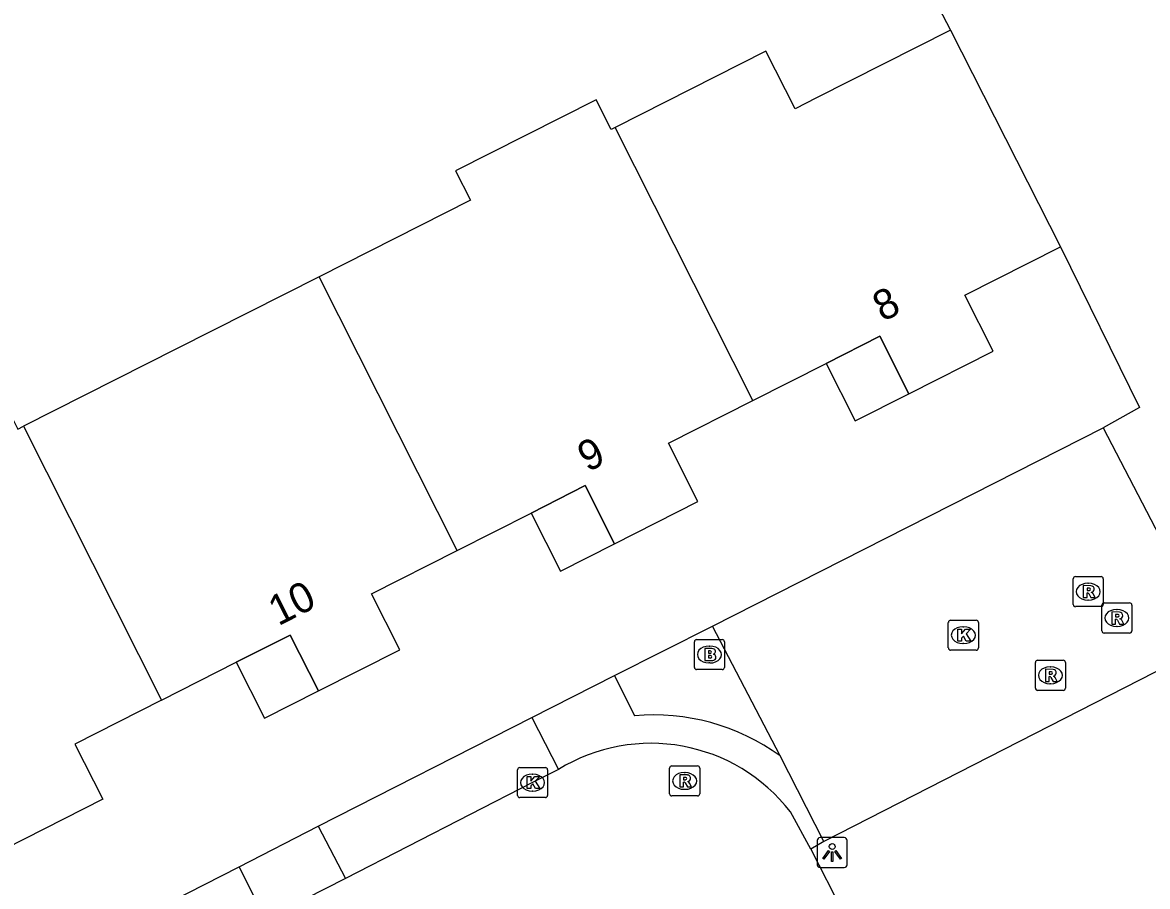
# Model space of a CAD drawing. Extents: x 162722 to 165099, y 384721 to 386283.
# Drawn here: x 163760.63 to 163798.08, y 385010.64 to 385039.4 of the extents above; entities that cross this region are included whole.
import ezdxf

# ---------------------------------------------------------------- set-up
doc = ezdxf.new("R2010")
doc.units = 0
for name, color, linetype in [('IMGEO_Brandkraan', 7, 'Continuous'), ('IMGEO_Groenvoorziening', 7, 'Continuous'), ('IMGEO_Kolk', 7, 'Continuous'), ('IMGEO_Lichtpunt', 7, 'Continuous'), ('IMGEO_Pand', 7, 'Continuous'), ('IMGEO_Pand_nummerreeks', 7, 'Continuous'), ('IMGEO_Pand_overbouw', 7, 'Continuous'), ('IMGEO_Rijbaan_lokaal_open', 7, 'Continuous'), ('IMGEO_Rioolput', 7, 'Continuous'), ('IMGEO_Voetpad_open', 7, 'Continuous')]:
    doc.layers.add(name, color=color, linetype=linetype)

msp = doc.modelspace()

# ---------------------------------------------------------------- linework, layer by layer
at = {"layer": 'IMGEO_Brandkraan'}
for p, q in [((163783.072, 385018.863), (163783.924, 385018.863)), ((163782.997, 385017.937), (163782.997, 385018.789)), ((163783.485, 385018.643), (163783.51, 385018.643)), ((163783.998, 385018.789), (163783.998, 385017.937)), ((163783.924, 385017.863), (163783.072, 385017.863)), ((163783.508, 385018.083), (163783.483, 385018.083))]:
    msp.add_line(p, q, dxfattribs=at)
for points in [[(163783.072, 385018.863), (163783.924, 385018.863)], [(163782.997, 385017.937), (163782.997, 385018.789)], [(163783.345, 385018.563), (163783.345, 385018.163), (163783.558, 385018.163)], [(163783.576, 385018.563), (163783.345, 385018.563)], [(163783.524, 385018.482), (163783.47, 385018.482), (163783.47, 385018.406)], [(163783.998, 385018.789), (163783.998, 385017.937)], [(163783.47, 385018.406), (163783.523, 385018.406)], [(163783.532, 385018.33), (163783.47, 385018.33), (163783.47, 385018.249)], [(163783.47, 385018.249), (163783.532, 385018.249)], [(163783.924, 385017.863), (163783.072, 385017.863)]]:
    msp.add_lwpolyline(points, dxfattribs=at)
for centre, radius, start, end in [((163783.074, 385018.787), 0.0765, 91.552, 178.448), ((163783.074, 385018.787), 0.0765, 91.552, 178.448), ((163783.922, 385018.787), 0.0765, 1.552, 88.448), ((163783.922, 385018.787), 0.0765, 1.552, 88.448), ((163783.525, 385018.444), 0.0379, 267.8285, 90.9355), ((163783.58, 385018.418), 0.145, 59.4692, 91.5367), ((163783.605, 385018.465), 0.0922, 285.5137, 58.1501), ((163783.533, 385018.289), 0.0404, 269.8759, 90.5077), ((163783.564, 385018.414), 0.251, 268.6676, 293.5347), ((163783.61, 385018.273), 0.105, 301.3115, 78.989), ((163783.074, 385017.939), 0.0765, 181.552, 268.448), ((163783.074, 385017.939), 0.0765, 181.552, 268.448), ((163783.922, 385017.939), 0.0765, 271.552, 358.448), ((163783.922, 385017.939), 0.0765, 271.552, 358.448)]:
    msp.add_arc(centre, radius, start, end, dxfattribs=at)
for centre, major_axis, ratio, start_param, end_param in [((163783.484, 385018.363), (-0.387, 0.002), 0.722429, 4.712389, 7.853982), ((163783.509, 385018.363), (-0.39, 0.002), 0.717154, 1.570796, 4.712389)]:
    msp.add_ellipse(centre, major_axis=major_axis, ratio=ratio, start_param=start_param, end_param=end_param, dxfattribs=at)
at = {"layer": 'IMGEO_Groenvoorziening'}
for points in [[(163783.871, 385053.812), (163791.526, 385039.145)], [(163795.181, 385031.929), (163797.817, 385026.586), (163796.607, 385025.906)]]:
    msp.add_lwpolyline(points, dxfattribs=at)
at = {"layer": 'IMGEO_Kolk'}
for p, q in [((163791.449, 385018.582), (163791.449, 385019.434)), ((163791.524, 385019.508), (163792.376, 385019.508)), ((163791.937, 385019.288), (163791.962, 385019.288)), ((163792.45, 385019.434), (163792.45, 385018.582)), ((163792.376, 385018.508), (163791.524, 385018.508)), ((163791.96, 385018.728), (163791.935, 385018.728)), ((163777.11, 385013.676), (163777.11, 385014.528)), ((163777.185, 385014.602), (163778.037, 385014.602)), ((163777.598, 385014.382), (163777.623, 385014.382)), ((163778.111, 385014.528), (163778.111, 385013.676)), ((163778.037, 385013.602), (163777.185, 385013.602)), ((163777.621, 385013.822), (163777.596, 385013.822))]:
    msp.add_line(p, q, dxfattribs=at)
for points in [[(163791.449, 385018.582), (163791.449, 385019.434)], [(163791.524, 385019.508), (163792.376, 385019.508)], [(163792.45, 385019.434), (163792.45, 385018.582)], [(163791.77, 385019.208), (163791.893, 385019.208), (163791.893, 385019.057), (163792.023, 385019.208), (163792.187, 385019.208), (163792.041, 385019.057), (163792.194, 385018.808), (163792.042, 385018.808), (163791.957, 385018.972), (163791.893, 385018.905), (163791.893, 385018.808), (163791.77, 385018.808), (163791.77, 385019.208)], [(163792.376, 385018.508), (163791.524, 385018.508)], [(163777.11, 385013.676), (163777.11, 385014.528)], [(163777.185, 385014.602), (163778.037, 385014.602)], [(163778.111, 385014.528), (163778.111, 385013.676)], [(163777.431, 385014.302), (163777.554, 385014.302), (163777.554, 385014.151), (163777.684, 385014.302), (163777.848, 385014.302), (163777.702, 385014.151), (163777.855, 385013.902), (163777.703, 385013.902), (163777.618, 385014.066), (163777.554, 385013.999), (163777.554, 385013.902), (163777.431, 385013.902), (163777.431, 385014.302)], [(163778.037, 385013.602), (163777.185, 385013.602)]]:
    msp.add_lwpolyline(points, dxfattribs=at)
for centre, start, end in [((163791.526, 385019.432), 91.552, 178.448), ((163791.526, 385019.432), 91.552, 178.448), ((163792.374, 385019.432), 1.552, 88.448), ((163792.374, 385019.432), 1.552, 88.448), ((163791.526, 385018.584), 181.552, 268.448), ((163791.526, 385018.584), 181.552, 268.448), ((163792.374, 385018.584), 271.552, 358.448), ((163792.374, 385018.584), 271.552, 358.448), ((163777.187, 385014.526), 91.552, 178.448), ((163777.187, 385014.526), 91.552, 178.448), ((163778.035, 385014.526), 1.552, 88.448), ((163778.035, 385014.526), 1.552, 88.448), ((163777.187, 385013.678), 181.552, 268.448), ((163777.187, 385013.678), 181.552, 268.448), ((163778.035, 385013.678), 271.552, 358.448), ((163778.035, 385013.678), 271.552, 358.448)]:
    msp.add_arc(centre, 0.0765, start, end, dxfattribs=at)
for centre, major_axis, ratio, start_param, end_param in [((163791.936, 385019.008), (-0.387, 0.002), 0.722429, 4.712389, 7.853982), ((163791.961, 385019.008), (-0.39, 0.002), 0.717154, 1.570796, 4.712389), ((163777.597, 385014.102), (-0.387, 0.002), 0.722429, 4.712389, 7.853982), ((163777.622, 385014.102), (-0.39, 0.002), 0.717154, 1.570796, 4.712389)]:
    msp.add_ellipse(centre, major_axis=major_axis, ratio=ratio, start_param=start_param, end_param=end_param, dxfattribs=at)
at = {"layer": 'IMGEO_Lichtpunt'}
for p, q in [((163787.085, 385012.177), (163787.085, 385011.37)), ((163787.085, 385012.177), (163787.085, 385011.37)), ((163787.987, 385012.272), (163787.179, 385012.272)), ((163787.987, 385012.272), (163787.179, 385012.272)), ((163788.081, 385011.37), (163788.081, 385012.177)), ((163788.081, 385011.37), (163788.081, 385012.177)), ((163787.179, 385011.276), (163787.987, 385011.276)), ((163787.179, 385011.276), (163787.987, 385011.276))]:
    msp.add_line(p, q, dxfattribs=at)
for points in [[(163787.459, 385011.841), (163787.498, 385011.813), (163787.31, 385011.551), (163787.272, 385011.578), (163787.459, 385011.841)], [(163787.561, 385011.793), (163787.608, 385011.793), (163787.608, 385011.471), (163787.561, 385011.471), (163787.561, 385011.793)], [(163787.671, 385011.813), (163787.709, 385011.84), (163787.896, 385011.578), (163787.857, 385011.55), (163787.671, 385011.813)]]:
    msp.add_lwpolyline(points, dxfattribs=at)
msp.add_circle((163787.584, 385011.975), 0.0994, dxfattribs=at)
for centre, start, end in [((163787.179, 385012.177), 90, 180), ((163787.179, 385012.177), 90, 180), ((163787.987, 385012.177), 0, 90), ((163787.987, 385012.177), 0, 90), ((163787.179, 385011.37), 180, 270), ((163787.179, 385011.37), 180, 270), ((163787.987, 385011.37), 270, 0), ((163787.987, 385011.37), 270, 360)]:
    msp.add_arc(centre, 0.0946, start, end, dxfattribs=at)
at = {"layer": 'IMGEO_Pand'}
for points in [[(163791.526, 385039.145), (163787.066, 385036.886), (163786.353, 385036.525), (163785.38, 385038.447), (163780.362, 385035.906)], [(163791.526, 385039.145), (163795.181, 385031.929)], [(163780.362, 385035.906), (163780.224, 385035.836), (163779.723, 385036.826), (163775.048, 385034.459), (163775.544, 385033.48), (163770.511, 385030.931)], [(163784.94, 385026.815), (163780.362, 385035.906)], [(163784.94, 385026.815), (163787.381, 385028.051), (163789.168, 385028.956), (163790.137, 385027.041), (163792.939, 385028.461), (163791.999, 385030.318), (163795.181, 385031.929)], [(163770.511, 385030.931), (163765.78, 385028.549), (163760.67, 385025.961)], [(163775.097, 385021.825), (163770.511, 385030.931)], [(163765.26, 385016.849), (163762.37, 385015.385), (163763.301, 385013.546), (163758.739, 385011.235), (163753.192, 385022.186), (163755.881, 385023.548), (163756.343, 385024.825), (163760.057, 385026.705), (163760.482, 385025.866), (163760.67, 385025.961)], [(163775.097, 385021.825), (163777.559, 385023.072), (163779.361, 385023.985), (163780.34, 385022.052), (163783.112, 385023.456), (163782.132, 385025.393), (163784.94, 385026.815)], [(163760.67, 385025.961), (163765.26, 385016.849)], [(163765.26, 385016.849), (163767.743, 385018.107), (163769.542, 385019.006), (163770.481, 385017.153), (163773.192, 385018.525), (163772.25, 385020.384), (163775.097, 385021.825)]]:
    msp.add_lwpolyline(points, dxfattribs=at)
at = {"layer": 'IMGEO_Pand_overbouw'}
for points in [[(163789.168, 385028.956), (163787.381, 385028.051), (163788.35, 385026.136), (163790.137, 385027.041)], [(163779.361, 385023.985), (163777.559, 385023.072), (163778.538, 385021.139), (163780.34, 385022.052)], [(163769.542, 385019.006), (163767.743, 385018.107), (163768.687, 385016.244), (163770.481, 385017.153)]]:
    msp.add_lwpolyline(points, close=True, dxfattribs=at)
at = {"layer": 'IMGEO_Rijbaan_lokaal_open'}
for points in [[(163783.595, 385019.308), (163796.607, 385025.906)], [(163796.607, 385025.906), (163799.345, 385020.634), (163799.657, 385020.033)], [(163785.848, 385014.991), (163783.595, 385019.308)], [(163800.305, 385018.786), (163787.306, 385012.139)], [(163787.306, 385012.139), (163785.848, 385014.991)], [(163778.469, 385014.536), (163777.611, 385014.102), (163771.379, 385010.915)], [(163786.877, 385011.884), (163786.194, 385013.124)], [(163786.877, 385011.884), (163792.143, 385001.568), (163792.25, 385001.396)], [(163771.379, 385010.915), (163768.724, 385009.555)]]:
    msp.add_lwpolyline(points, dxfattribs=at)
msp.add_arc((163781.548, 385009.542), 5.867, 37.6313, 121.652, dxfattribs=at)
at = {"layer": 'IMGEO_Rioolput'}
for p, q in [((163795.605, 385020.031), (163795.605, 385020.883)), ((163795.68, 385020.957), (163796.532, 385020.957)), ((163796.093, 385020.737), (163796.118, 385020.737)), ((163796.606, 385020.883), (163796.606, 385020.031)), ((163796.116, 385020.177), (163796.091, 385020.177)), ((163796.558, 385019.154), (163796.558, 385020.006)), ((163796.633, 385020.08), (163797.485, 385020.08)), ((163797.559, 385020.006), (163797.559, 385019.154)), ((163796.532, 385019.957), (163795.68, 385019.957)), ((163797.046, 385019.86), (163797.071, 385019.86)), ((163797.069, 385019.3), (163797.044, 385019.3)), ((163797.485, 385019.08), (163796.633, 385019.08)), ((163794.346, 385017.246), (163794.346, 385018.098)), ((163794.421, 385018.172), (163795.273, 385018.172)), ((163795.347, 385018.098), (163795.347, 385017.246)), ((163794.834, 385017.952), (163794.859, 385017.952)), ((163794.857, 385017.392), (163794.832, 385017.392)), ((163795.273, 385017.172), (163794.421, 385017.172)), ((163782.173, 385013.732), (163782.173, 385014.584)), ((163782.248, 385014.658), (163783.1, 385014.658)), ((163782.661, 385014.438), (163782.686, 385014.438)), ((163783.174, 385014.584), (163783.174, 385013.732)), ((163783.1, 385013.658), (163782.248, 385013.658)), ((163782.684, 385013.878), (163782.659, 385013.878))]:
    msp.add_line(p, q, dxfattribs=at)
for points in [[(163795.605, 385020.031), (163795.605, 385020.883)], [(163795.68, 385020.957), (163796.532, 385020.957)], [(163796.606, 385020.883), (163796.606, 385020.031)], [(163796.194, 385020.655), (163795.942, 385020.657), (163795.942, 385020.257)], [(163795.942, 385020.257), (163796.066, 385020.257), (163796.066, 385020.419), (163796.077, 385020.419)], [(163796.12, 385020.576), (163796.066, 385020.576), (163796.066, 385020.495)], [(163796.066, 385020.495), (163796.118, 385020.495)], [(163796.124, 385020.39), (163796.195, 385020.257), (163796.335, 385020.257), (163796.27, 385020.383)], [(163796.558, 385019.154), (163796.558, 385020.006)], [(163796.633, 385020.08), (163797.485, 385020.08)], [(163797.559, 385020.006), (163797.559, 385019.154)], [(163796.532, 385019.957), (163795.68, 385019.957)], [(163797.147, 385019.778), (163796.895, 385019.78), (163796.895, 385019.38)], [(163797.073, 385019.699), (163797.019, 385019.699), (163797.019, 385019.618)], [(163797.019, 385019.618), (163797.071, 385019.618)], [(163796.895, 385019.38), (163797.019, 385019.38), (163797.019, 385019.542), (163797.03, 385019.542)], [(163797.077, 385019.513), (163797.148, 385019.38), (163797.288, 385019.38), (163797.223, 385019.506)], [(163797.485, 385019.08), (163796.633, 385019.08)], [(163794.346, 385017.246), (163794.346, 385018.098)], [(163794.421, 385018.172), (163795.273, 385018.172)], [(163795.347, 385018.098), (163795.347, 385017.246)], [(163794.935, 385017.87), (163794.683, 385017.872), (163794.683, 385017.472)], [(163794.861, 385017.791), (163794.807, 385017.791), (163794.807, 385017.71)], [(163794.683, 385017.472), (163794.807, 385017.472), (163794.807, 385017.634), (163794.818, 385017.634)], [(163794.807, 385017.71), (163794.859, 385017.71)], [(163794.865, 385017.605), (163794.936, 385017.472), (163795.076, 385017.472), (163795.011, 385017.598)], [(163795.273, 385017.172), (163794.421, 385017.172)], [(163782.173, 385013.732), (163782.173, 385014.584)], [(163782.248, 385014.658), (163783.1, 385014.658)], [(163782.762, 385014.356), (163782.51, 385014.358), (163782.51, 385013.958)], [(163783.174, 385014.584), (163783.174, 385013.732)], [(163782.51, 385013.958), (163782.634, 385013.958), (163782.634, 385014.12), (163782.645, 385014.12)], [(163782.688, 385014.277), (163782.634, 385014.277), (163782.634, 385014.196)], [(163782.634, 385014.196), (163782.686, 385014.196)], [(163782.692, 385014.091), (163782.763, 385013.958), (163782.903, 385013.958), (163782.838, 385014.084)], [(163783.1, 385013.658), (163782.248, 385013.658)]]:
    msp.add_lwpolyline(points, dxfattribs=at)
for centre, radius, start, end in [((163795.682, 385020.881), 0.0765, 91.552, 178.448), ((163795.682, 385020.881), 0.0765, 91.552, 178.448), ((163796.53, 385020.881), 0.0765, 1.552, 88.448), ((163796.53, 385020.881), 0.0765, 1.552, 88.448), ((163796.076, 385020.366), 0.0533, 26.0293, 88.6989), ((163796.102, 385020.684), 0.19, 274.7715, 282.9687), ((163796.126, 385020.48), 0.0964, 77.0061, 93.1865), ((163796.14, 385020.537), 0.0378, 276.6634, 79.6772), ((163796.193, 385020.545), 0.109, 350.3612, 89.416), ((163796.191, 385020.545), 0.112, 277.5842, 350.9817), ((163796.175, 385020.33), 0.108, 29.5134, 73.7905), ((163795.682, 385020.033), 0.0765, 181.552, 268.448), ((163795.682, 385020.033), 0.0765, 181.552, 268.448), ((163796.53, 385020.033), 0.0765, 271.552, 358.448), ((163796.53, 385020.033), 0.0765, 271.552, 358.448), ((163796.635, 385020.004), 0.0765, 91.552, 178.448), ((163796.635, 385020.004), 0.0765, 91.552, 178.448), ((163797.483, 385020.004), 0.0765, 1.552, 88.448), ((163797.483, 385020.004), 0.0765, 1.552, 88.448), ((163797.055, 385019.807), 0.19, 274.7715, 282.9687), ((163797.079, 385019.603), 0.0964, 77.0061, 93.1865), ((163797.093, 385019.66), 0.0378, 276.6634, 79.6772), ((163797.146, 385019.668), 0.109, 350.3612, 89.416), ((163797.144, 385019.668), 0.112, 277.5842, 350.9817), ((163797.029, 385019.489), 0.0533, 26.0293, 88.6989), ((163797.128, 385019.453), 0.108, 29.5134, 73.7905), ((163796.635, 385019.156), 0.0765, 181.552, 268.448), ((163796.635, 385019.156), 0.0765, 181.552, 268.448), ((163797.483, 385019.156), 0.0765, 271.552, 358.448), ((163797.483, 385019.156), 0.0765, 271.552, 358.448), ((163794.423, 385018.096), 0.0765, 91.552, 178.448), ((163794.423, 385018.096), 0.0765, 91.552, 178.448), ((163795.271, 385018.096), 0.0765, 1.552, 88.448), ((163795.271, 385018.096), 0.0765, 1.552, 88.448), ((163794.843, 385017.899), 0.19, 274.7715, 282.9687), ((163794.867, 385017.695), 0.0964, 77.0061, 93.1865), ((163794.881, 385017.752), 0.0378, 276.6634, 79.6772), ((163794.934, 385017.76), 0.109, 350.3612, 89.416), ((163794.932, 385017.76), 0.112, 277.5842, 350.9817), ((163794.817, 385017.581), 0.0533, 26.0293, 88.6989), ((163794.916, 385017.545), 0.108, 29.5134, 73.7905), ((163794.423, 385017.248), 0.0765, 181.552, 268.448), ((163794.423, 385017.248), 0.0765, 181.552, 268.448), ((163795.271, 385017.248), 0.0765, 271.552, 358.448), ((163795.271, 385017.248), 0.0765, 271.552, 358.448), ((163782.25, 385014.582), 0.0765, 91.552, 178.448), ((163782.25, 385014.582), 0.0765, 91.552, 178.448), ((163782.761, 385014.246), 0.109, 350.3612, 89.416), ((163783.098, 385014.582), 0.0765, 1.552, 88.448), ((163783.098, 385014.582), 0.0765, 1.552, 88.448), ((163782.644, 385014.067), 0.0533, 26.0293, 88.6989), ((163782.67, 385014.385), 0.19, 274.7715, 282.9687), ((163782.694, 385014.181), 0.0964, 77.0061, 93.1865), ((163782.708, 385014.238), 0.0378, 276.6634, 79.6772), ((163782.759, 385014.246), 0.112, 277.5842, 350.9817), ((163782.743, 385014.031), 0.108, 29.5134, 73.7905), ((163782.25, 385013.734), 0.0765, 181.552, 268.448), ((163782.25, 385013.734), 0.0765, 181.552, 268.448), ((163783.098, 385013.734), 0.0765, 271.552, 358.448), ((163783.098, 385013.734), 0.0765, 271.552, 358.448)]:
    msp.add_arc(centre, radius, start, end, dxfattribs=at)
for centre, major_axis, ratio, start_param, end_param in [((163796.092, 385020.457), (-0.387, 0.002), 0.722429, 4.712389, 7.853982), ((163796.117, 385020.457), (-0.39, 0.002), 0.717154, 1.570796, 4.712389), ((163797.045, 385019.58), (-0.387, 0.002), 0.722429, 4.712389, 7.853982), ((163797.07, 385019.58), (-0.39, 0.002), 0.717154, 1.570796, 4.712389), ((163794.833, 385017.672), (-0.387, 0.002), 0.722429, 4.712389, 7.853982), ((163794.858, 385017.672), (-0.39, 0.002), 0.717154, 1.570796, 4.712389), ((163782.66, 385014.158), (-0.387, 0.002), 0.722429, 4.712389, 7.853982), ((163782.685, 385014.158), (-0.39, 0.002), 0.717154, 1.570796, 4.712389)]:
    msp.add_ellipse(centre, major_axis=major_axis, ratio=ratio, start_param=start_param, end_param=end_param, dxfattribs=at)
at = {"layer": 'IMGEO_Voetpad_open'}
for points in [[(163780.334, 385017.664), (163783.595, 385019.308)], [(163777.584, 385016.272), (163780.334, 385017.664)], [(163780.334, 385017.664), (163781.003, 385016.322)], [(163770.469, 385012.653), (163777.584, 385016.272)], [(163777.584, 385016.272), (163778.469, 385014.536)], [(163767.841, 385011.304), (163770.469, 385012.653)], [(163770.469, 385012.653), (163771.379, 385010.915)], [(163787.306, 385012.139), (163786.877, 385011.884)], [(163757.459, 385006.177), (163757.517, 385006.039), (163767.841, 385011.304)], [(163768.724, 385009.555), (163767.841, 385011.304)]]:
    msp.add_lwpolyline(points, dxfattribs=at)
msp.add_arc((163781.665, 385009.246), 7.106, 53.9363, 95.3415, dxfattribs=at)

# ---------------------------------------------------------------- texts
at = {"layer": 'IMGEO_Pand_nummerreeks'}
for s, rotation, p in [('8', 26.8717, (163789.264, 385029.423)), ('9', 26.866, (163779.442, 385024.421)), ('10', 26.8545, (163769.148, 385019.302))]:
    msp.add_text(s, height=1, rotation=rotation, dxfattribs=at).set_placement(p)

doc.saveas('drawing.dxf')
